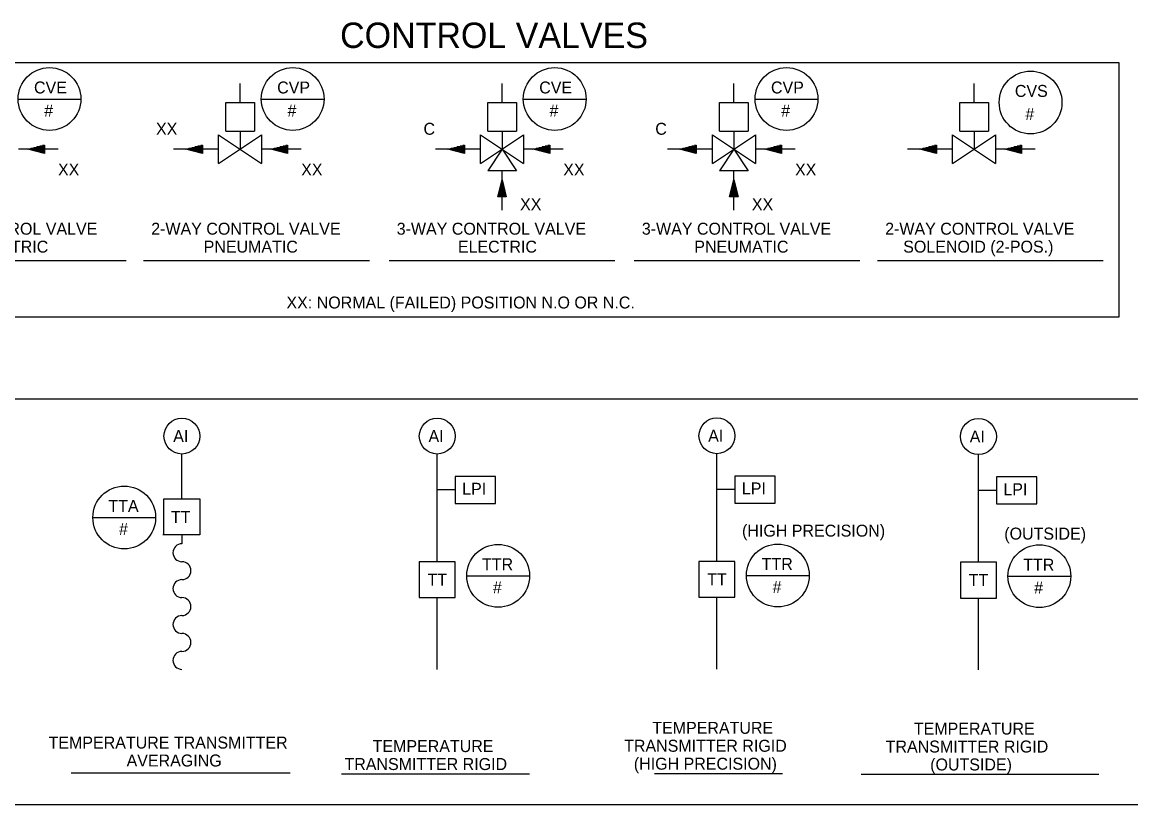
# Model space of a CAD drawing. Extents: x 10015 to 10283, y 10002 to 10184.
# Drawn here: x 10065.3 to 10127.1, y 10136.4 to 10180 of the extents above; entities that cross this region are included whole.
import ezdxf

# ---------------------------------------------------------------- set-up
doc = ezdxf.new("R2010")
doc.units = 0
for name, color, linetype in [('G-ANNO-TEXT', 7, 'Continuous'), ('G-DETL-LINE', 7, 'Continuous'), ('G-DETL-TEXT', 7, 'Continuous'), ('M-ANNO-NPLT', 7, 'Continuous')]:
    doc.layers.add(name, color=color, linetype=linetype)

msp = doc.modelspace()

# ---------------------------------------------------------------- linework, layer by layer
at = {"layer": 'G-ANNO-TEXT'}
for p, q in [((10058.48, 10166.726), (10071.068, 10166.726)), ((10072.036, 10166.726), (10084.623, 10166.726)), ((10085.718, 10166.726), (10098.306, 10166.726)), ((10099.382, 10166.726), (10111.969, 10166.726)), ((10112.942, 10166.726), (10125.53, 10166.726)), ((10068.004, 10138.166), (10080.21, 10138.166)), ((10083.069, 10138.112), (10093.555, 10138.112)), ((10100.508, 10138.131), (10107.643, 10138.131)), ((10112.033, 10138.088), (10125.289, 10138.088))]:
    msp.add_line(p, q, dxfattribs=at)
at = {"layer": 'G-DETL-LINE'}
for p, q in [((10076.618, 10173.927), (10076.618, 10175.527)), ((10076.618, 10175.527), (10078.218, 10175.527)), ((10078.218, 10175.527), (10078.218, 10173.927)), ((10091.223, 10173.927), (10091.223, 10175.527)), ((10091.223, 10175.527), (10092.823, 10175.527)), ((10092.823, 10175.527), (10092.823, 10173.927)), ((10104.142, 10173.927), (10104.142, 10175.527)), ((10104.142, 10175.527), (10105.742, 10175.527)), ((10105.742, 10175.527), (10105.742, 10173.927)), ((10117.525, 10173.927), (10117.525, 10175.527)), ((10117.525, 10175.527), (10119.125, 10175.527)), ((10119.125, 10175.527), (10119.125, 10173.927)), ((10076.218, 10173.725), (10078.618, 10172.125)), ((10076.218, 10172.125), (10076.218, 10173.725)), ((10076.218, 10172.125), (10078.618, 10173.725)), ((10076.618, 10173.927), (10078.218, 10173.927)), ((10077.418, 10173.927), (10077.418, 10172.925)), ((10078.618, 10173.725), (10078.618, 10172.125)), ((10090.823, 10173.725), (10093.223, 10172.125)), ((10090.823, 10172.125), (10090.823, 10173.725)), ((10090.823, 10172.125), (10093.223, 10173.725)), ((10091.223, 10173.927), (10092.823, 10173.927)), ((10092.023, 10173.927), (10092.023, 10172.925)), ((10093.223, 10173.725), (10093.223, 10172.125)), ((10103.742, 10173.725), (10106.142, 10172.125)), ((10103.742, 10172.125), (10103.742, 10173.725)), ((10103.742, 10172.125), (10106.142, 10173.725)), ((10104.142, 10173.927), (10105.742, 10173.927)), ((10104.942, 10173.927), (10104.942, 10172.925)), ((10106.142, 10173.725), (10106.142, 10172.125)), ((10117.125, 10173.725), (10119.525, 10172.125)), ((10117.125, 10172.125), (10117.125, 10173.725)), ((10117.125, 10172.125), (10119.525, 10173.725)), ((10117.525, 10173.927), (10119.125, 10173.927)), ((10118.325, 10173.927), (10118.325, 10172.925)), ((10119.525, 10173.725), (10119.525, 10172.125)), ((10067.269, 10172.925), (10065.063, 10172.925)), ((10066.512, 10172.92), (10065.579, 10172.92)), ((10066.512, 10172.961), (10065.757, 10172.961)), ((10066.512, 10173.003), (10065.928, 10173.003)), ((10066.512, 10173.045), (10066.094, 10173.045)), ((10066.512, 10173.086), (10066.259, 10173.086)), ((10066.512, 10173.128), (10066.411, 10173.128)), ((10076.218, 10172.925), (10073.708, 10172.925)), ((10075.324, 10172.92), (10074.39, 10172.92)), ((10075.324, 10172.961), (10074.569, 10172.961)), ((10075.324, 10173.003), (10074.739, 10173.003)), ((10075.324, 10173.045), (10074.906, 10173.045)), ((10075.324, 10173.086), (10075.071, 10173.086)), ((10075.324, 10173.128), (10075.222, 10173.128)), ((10080.824, 10172.925), (10078.618, 10172.925)), ((10080.067, 10172.92), (10079.134, 10172.92)), ((10080.067, 10172.961), (10079.312, 10172.961)), ((10080.067, 10173.003), (10079.483, 10173.003)), ((10080.067, 10173.045), (10079.65, 10173.045)), ((10080.067, 10173.086), (10079.815, 10173.086)), ((10080.067, 10173.128), (10079.966, 10173.128)), ((10090.823, 10172.925), (10088.314, 10172.925)), ((10089.929, 10172.92), (10088.996, 10172.92)), ((10089.929, 10172.961), (10089.174, 10172.961)), ((10089.929, 10173.003), (10089.344, 10173.003)), ((10089.929, 10173.045), (10089.511, 10173.045)), ((10089.929, 10173.086), (10089.676, 10173.086)), ((10089.929, 10173.128), (10089.828, 10173.128)), ((10092.023, 10172.925), (10091.223, 10171.725)), ((10092.023, 10172.925), (10092.823, 10171.725)), ((10095.429, 10172.925), (10093.223, 10172.925)), ((10094.673, 10172.92), (10093.739, 10172.92)), ((10094.673, 10172.961), (10093.918, 10172.961)), ((10094.673, 10173.003), (10094.088, 10173.003)), ((10094.673, 10173.045), (10094.255, 10173.045)), ((10094.673, 10173.086), (10094.42, 10173.086)), ((10094.673, 10173.128), (10094.571, 10173.128)), ((10103.742, 10172.925), (10101.232, 10172.925)), ((10102.847, 10172.92), (10101.914, 10172.92)), ((10102.847, 10172.961), (10102.092, 10172.961)), ((10102.847, 10173.003), (10102.263, 10173.003)), ((10102.847, 10173.045), (10102.43, 10173.045)), ((10102.847, 10173.086), (10102.594, 10173.086)), ((10102.847, 10173.128), (10102.746, 10173.128)), ((10104.942, 10172.925), (10104.142, 10171.725)), ((10104.942, 10172.925), (10105.742, 10171.725)), ((10108.348, 10172.925), (10106.142, 10172.925)), ((10107.591, 10172.92), (10106.658, 10172.92)), ((10107.591, 10172.961), (10106.836, 10172.961)), ((10107.591, 10173.003), (10107.007, 10173.003)), ((10107.591, 10173.045), (10107.173, 10173.045)), ((10107.591, 10173.086), (10107.338, 10173.086)), ((10107.591, 10173.128), (10107.49, 10173.128)), ((10117.125, 10172.925), (10114.615, 10172.925)), ((10116.23, 10172.92), (10115.297, 10172.92)), ((10116.23, 10172.961), (10115.475, 10172.961)), ((10116.23, 10173.003), (10115.646, 10173.003)), ((10116.23, 10173.045), (10115.813, 10173.045)), ((10116.23, 10173.086), (10115.977, 10173.086)), ((10116.23, 10173.128), (10116.129, 10173.128)), ((10121.73, 10172.925), (10119.525, 10172.925)), ((10120.974, 10172.92), (10120.041, 10172.92)), ((10120.974, 10172.961), (10120.219, 10172.961)), ((10120.974, 10173.003), (10120.39, 10173.003)), ((10120.974, 10173.045), (10120.556, 10173.045)), ((10120.974, 10173.086), (10120.721, 10173.086)), ((10120.974, 10173.128), (10120.873, 10173.128)), ((10066.512, 10172.878), (10065.757, 10172.878)), ((10066.512, 10172.836), (10065.928, 10172.836)), ((10066.512, 10172.795), (10066.094, 10172.795)), ((10066.512, 10172.753), (10066.259, 10172.753)), ((10066.512, 10172.711), (10066.411, 10172.711)), ((10075.324, 10172.878), (10074.569, 10172.878)), ((10075.324, 10172.836), (10074.739, 10172.836)), ((10075.324, 10172.795), (10074.906, 10172.795)), ((10075.324, 10172.753), (10075.071, 10172.753)), ((10075.324, 10172.711), (10075.222, 10172.711)), ((10080.067, 10172.878), (10079.312, 10172.878)), ((10080.067, 10172.836), (10079.483, 10172.836)), ((10080.067, 10172.795), (10079.65, 10172.795)), ((10080.067, 10172.753), (10079.815, 10172.753)), ((10080.067, 10172.711), (10079.966, 10172.711)), ((10089.929, 10172.878), (10089.174, 10172.878)), ((10089.929, 10172.836), (10089.344, 10172.836)), ((10089.929, 10172.795), (10089.511, 10172.795)), ((10089.929, 10172.753), (10089.676, 10172.753)), ((10089.929, 10172.711), (10089.828, 10172.711)), ((10094.673, 10172.878), (10093.918, 10172.878)), ((10094.673, 10172.836), (10094.088, 10172.836)), ((10094.673, 10172.795), (10094.255, 10172.795)), ((10094.673, 10172.753), (10094.42, 10172.753)), ((10094.673, 10172.711), (10094.571, 10172.711)), ((10102.847, 10172.878), (10102.092, 10172.878)), ((10102.847, 10172.836), (10102.263, 10172.836)), ((10102.847, 10172.795), (10102.43, 10172.795)), ((10102.847, 10172.753), (10102.594, 10172.753)), ((10102.847, 10172.711), (10102.746, 10172.711)), ((10107.591, 10172.878), (10106.836, 10172.878)), ((10107.591, 10172.836), (10107.007, 10172.836)), ((10107.591, 10172.795), (10107.173, 10172.795)), ((10107.591, 10172.753), (10107.338, 10172.753)), ((10107.591, 10172.711), (10107.49, 10172.711)), ((10116.23, 10172.878), (10115.475, 10172.878)), ((10116.23, 10172.836), (10115.646, 10172.836)), ((10116.23, 10172.795), (10115.813, 10172.795)), ((10116.23, 10172.753), (10115.977, 10172.753)), ((10116.23, 10172.711), (10116.129, 10172.711)), ((10120.974, 10172.878), (10120.219, 10172.878)), ((10120.974, 10172.836), (10120.39, 10172.836)), ((10120.974, 10172.795), (10120.556, 10172.795)), ((10120.974, 10172.753), (10120.721, 10172.753)), ((10120.974, 10172.711), (10120.873, 10172.711)), ((10092.823, 10171.725), (10091.223, 10171.725)), ((10092.023, 10169.519), (10092.023, 10171.725)), ((10105.742, 10171.725), (10104.142, 10171.725)), ((10104.942, 10169.519), (10104.942, 10171.725)), ((10092.018, 10170.275), (10092.018, 10171.208)), ((10104.937, 10170.275), (10104.937, 10171.208)), ((10091.852, 10170.275), (10091.852, 10170.528)), ((10091.893, 10170.275), (10091.893, 10170.693)), ((10091.935, 10170.275), (10091.935, 10170.86)), ((10091.977, 10170.275), (10091.977, 10171.03)), ((10092.06, 10170.275), (10092.06, 10171.03)), ((10092.102, 10170.275), (10092.102, 10170.86)), ((10092.143, 10170.275), (10092.143, 10170.693)), ((10092.185, 10170.275), (10092.185, 10170.528)), ((10104.77, 10170.275), (10104.77, 10170.528)), ((10104.812, 10170.275), (10104.812, 10170.693)), ((10104.853, 10170.275), (10104.853, 10170.86)), ((10104.895, 10170.275), (10104.895, 10171.03)), ((10104.978, 10170.275), (10104.978, 10171.03)), ((10105.02, 10170.275), (10105.02, 10170.86)), ((10105.062, 10170.275), (10105.062, 10170.693)), ((10105.103, 10170.275), (10105.103, 10170.528)), ((10091.81, 10170.275), (10091.81, 10170.376)), ((10092.227, 10170.275), (10092.227, 10170.376)), ((10104.728, 10170.275), (10104.728, 10170.376)), ((10105.145, 10170.275), (10105.145, 10170.376)), ((10074.177, 10153.434), (10074.177, 10155.934)), ((10088.408, 10149.934), (10088.408, 10155.934)), ((10103.995, 10149.953), (10103.995, 10155.953)), ((10118.572, 10149.91), (10118.572, 10155.91)), ((10091.658, 10154.684), (10089.408, 10154.684)), ((10089.408, 10154.684), (10089.408, 10153.184)), ((10091.658, 10153.184), (10091.658, 10154.684)), ((10107.245, 10154.703), (10104.995, 10154.703)), ((10104.995, 10154.703), (10104.995, 10153.203)), ((10107.245, 10153.203), (10107.245, 10154.703)), ((10121.822, 10154.66), (10119.572, 10154.66)), ((10119.572, 10154.66), (10119.572, 10153.16)), ((10121.822, 10153.16), (10121.822, 10154.66)), ((10089.408, 10153.934), (10088.408, 10153.934)), ((10104.995, 10153.953), (10103.995, 10153.953)), ((10119.572, 10153.91), (10118.572, 10153.91)), ((10073.177, 10153.434), (10075.177, 10153.434)), ((10073.177, 10151.434), (10073.177, 10153.434)), ((10075.177, 10153.434), (10075.177, 10151.434)), ((10089.408, 10153.184), (10091.658, 10153.184)), ((10104.995, 10153.203), (10107.245, 10153.203)), ((10119.572, 10153.16), (10121.822, 10153.16)), ((10075.177, 10151.434), (10073.121, 10151.434)), ((10074.177, 10151.434), (10074.177, 10150.934)), ((10087.408, 10149.934), (10087.408, 10147.934)), ((10089.408, 10149.934), (10087.408, 10149.934)), ((10089.408, 10147.934), (10089.408, 10149.934)), ((10102.995, 10149.953), (10102.995, 10147.953)), ((10104.995, 10149.953), (10102.995, 10149.953)), ((10104.995, 10147.953), (10104.995, 10149.953)), ((10117.572, 10149.91), (10117.572, 10147.91)), ((10119.572, 10149.91), (10117.572, 10149.91)), ((10119.572, 10147.91), (10119.572, 10149.91)), ((10087.408, 10147.934), (10089.408, 10147.934)), ((10088.408, 10143.934), (10088.408, 10147.934)), ((10102.995, 10147.953), (10104.995, 10147.953)), ((10103.995, 10143.953), (10103.995, 10147.953)), ((10117.572, 10147.91), (10119.572, 10147.91)), ((10118.572, 10143.91), (10118.572, 10147.91))]:
    msp.add_line(p, q, dxfattribs=at)
for points in [[(10057.424, 10177.757), (10126.391, 10177.757), (10126.391, 10163.559), (10057.424, 10163.559)], [(10066.512, 10172.686), (10065.579, 10172.92), (10066.512, 10173.153)], [(10075.324, 10172.686), (10074.39, 10172.92), (10075.324, 10173.153)], [(10080.067, 10172.686), (10079.134, 10172.92), (10080.067, 10173.153)], [(10089.929, 10172.686), (10088.996, 10172.92), (10089.929, 10173.153)], [(10094.673, 10172.686), (10093.739, 10172.92), (10094.673, 10173.153)], [(10102.847, 10172.686), (10101.914, 10172.92), (10102.847, 10173.153)], [(10107.591, 10172.686), (10106.658, 10172.92), (10107.591, 10173.153)], [(10116.23, 10172.686), (10115.297, 10172.92), (10116.23, 10173.153)], [(10120.974, 10172.686), (10120.041, 10172.92), (10120.974, 10173.153)], [(10091.785, 10170.275), (10092.018, 10171.208), (10092.252, 10170.275)], [(10104.703, 10170.275), (10104.937, 10171.208), (10105.17, 10170.275)], [(10015.495, 10159.007), (10161.797, 10159.007), (10161.797, 10136.385), (10015.495, 10136.385)]]:
    msp.add_lwpolyline(points, close=True, dxfattribs=at)
for centre in [(10074.177, 10156.934), (10088.408, 10156.934), (10103.995, 10156.953), (10118.572, 10156.91)]:
    msp.add_circle(centre, 1, dxfattribs=at)
for centre, start, end in [((10074.177, 10150.434), 90, 270), ((10074.177, 10149.434), 270, 90), ((10074.177, 10148.434), 90, 270), ((10074.177, 10147.434), 270, 90), ((10074.177, 10146.434), 90, 270), ((10074.177, 10145.434), 270, 90), ((10074.177, 10144.434), 90, 270)]:
    msp.add_arc(centre, 0.5, start, end, dxfattribs=at)
at = {"layer": 'G-DETL-TEXT'}
for centre in [(10066.793, 10175.719), (10080.349, 10175.719), (10094.954, 10175.719), (10107.872, 10175.719), (10121.478, 10175.527), (10070.962, 10152.399), (10091.802, 10149.149), (10107.389, 10149.168), (10121.966, 10149.125)]:
    msp.add_circle(centre, 1.75, dxfattribs=at)
at = {"layer": 'M-ANNO-NPLT'}
for p, q in [((10077.418, 10175.527), (10077.418, 10176.591)), ((10092.023, 10175.527), (10092.023, 10176.591)), ((10104.942, 10175.527), (10104.942, 10176.591)), ((10118.325, 10175.527), (10118.325, 10176.591)), ((10065.043, 10175.719), (10068.543, 10175.719)), ((10078.599, 10175.719), (10082.099, 10175.719)), ((10093.204, 10175.719), (10096.704, 10175.719)), ((10106.122, 10175.719), (10109.622, 10175.719)), ((10069.212, 10152.399), (10072.712, 10152.399)), ((10090.052, 10149.149), (10093.552, 10149.149)), ((10105.639, 10149.168), (10109.139, 10149.168)), ((10120.216, 10149.125), (10123.716, 10149.125))]:
    msp.add_line(p, q, dxfattribs=at)

# ---------------------------------------------------------------- texts
at = {"layer": 'G-ANNO-TEXT'}
for s, height, p in [('CONTROL VALVES', 1.41667, (10082.992, 10178.562)), ('XX', 0.6667, (10072.731, 10173.725)), ('C', 0.667, (10087.641, 10173.725)), ('C', 0.667, (10100.559, 10173.725)), ('XX', 0.6667, (10067.269, 10171.456)), ('XX', 0.6667, (10080.824, 10171.456)), ('XX', 0.6667, (10095.429, 10171.456)), ('XX', 0.6667, (10108.348, 10171.456)), ('XX', 0.6667, (10093.023, 10169.519)), ('XX', 0.6667, (10105.942, 10169.519)), ('2-WAY CONTROL VALVE', 0.66667, (10058.91, 10168.157)), ('2-WAY CONTROL VALVE', 0.66667, (10072.465, 10168.157)), ('3-WAY CONTROL VALVE', 0.66667, (10086.148, 10168.157)), ('3-WAY CONTROL VALVE', 0.66667, (10099.811, 10168.157)), ('2-WAY CONTROL VALVE', 0.66667, (10113.372, 10168.157)), ('ELECTRIC', 0.6667, (10062.318, 10167.157)), ('PNEUMATIC', 0.6667, (10075.388, 10167.157)), ('ELECTRIC', 0.6667, (10089.556, 10167.157)), ('PNEUMATIC', 0.6667, (10102.734, 10167.157)), ('SOLENOID (2-POS.)', 0.66667, (10114.378, 10167.157)), ('XX: NORMAL (FAILED) POSITION N.O OR N.C.', 0.66667, (10080.002, 10164.045)), ('TEMPERATURE', 0.66667, (10100.393, 10140.343)), ('TEMPERATURE', 0.66667, (10114.97, 10140.3)), ('TEMPERATURE TRANSMITTER', 0.66667, (10066.744, 10139.521)), ('TEMPERATURE', 0.66667, (10084.806, 10139.324)), ('TRANSMITTER RIGID', 0.66667, (10098.824, 10139.343)), ('TRANSMITTER RIGID', 0.66667, (10113.401, 10139.3)), ('AVERAGING', 0.6667, (10071.092, 10138.521)), ('TRANSMITTER RIGID', 0.66667, (10083.237, 10138.324)), ('(HIGH PRECISION)', 0.66667, (10099.364, 10138.343)), ('(OUTSIDE)', 0.6667, (10115.882, 10138.3))]:
    msp.add_text(s, height=height, dxfattribs=at).set_placement(p)
at = {"layer": 'G-DETL-LINE'}
for s, height, p in [('AI', 0.6667, (10073.69, 10156.6)), ('AI', 0.6667, (10087.921, 10156.6)), ('AI', 0.6667, (10103.508, 10156.62)), ('AI', 0.6667, (10118.085, 10156.577)), ('LPI', 0.6667, (10089.797, 10153.663)), ('LPI', 0.6667, (10105.384, 10153.682)), ('LPI', 0.6667, (10119.961, 10153.639)), ('TT', 0.6667, (10073.566, 10152.09)), ('(HIGH PRECISION)', 0.66667, (10105.394, 10151.331)), ('(OUTSIDE)', 0.6667, (10120.012, 10151.167)), ('TT', 0.6667, (10087.866, 10148.6)), ('TT', 0.6667, (10103.453, 10148.62)), ('TT', 0.6667, (10118.03, 10148.576))]:
    msp.add_text(s, height=height, dxfattribs=at).set_placement(p)
at = {"layer": 'G-DETL-TEXT'}
for s, height, p in [('CVE', 0.6667, (10065.931, 10176.027)), ('CVP', 0.6667, (10079.484, 10176.027)), ('CVE', 0.6667, (10094.091, 10176.027)), ('CVP', 0.6667, (10107.008, 10176.027)), ('CVS', 0.6667, (10120.602, 10175.836)), ('#', 0.667, (10066.503, 10174.743)), ('#', 0.667, (10080.059, 10174.743)), ('#', 0.667, (10094.664, 10174.743)), ('#', 0.667, (10107.582, 10174.743)), ('#', 0.667, (10121.188, 10174.552)), ('TTA', 0.6667, (10070.078, 10152.708)), ('#', 0.667, (10070.672, 10151.424)), ('TTR', 0.6667, (10090.903, 10149.458)), ('TTR', 0.6667, (10106.49, 10149.477)), ('TTR', 0.6667, (10121.067, 10149.434)), ('#', 0.667, (10091.512, 10148.174)), ('#', 0.667, (10107.099, 10148.193)), ('#', 0.667, (10121.676, 10148.15))]:
    msp.add_text(s, height=height, dxfattribs=at).set_placement(p)

doc.saveas('drawing.dxf')
